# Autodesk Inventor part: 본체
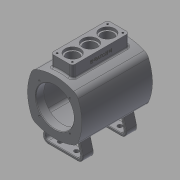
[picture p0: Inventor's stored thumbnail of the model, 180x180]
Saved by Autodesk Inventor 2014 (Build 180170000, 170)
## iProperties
Created: 2015-11
Part Number: 본체
Material: 일반
Document SubType Name: Modeling
Designer: mduedu
Density: 1 g/cm^3
Appearance: 기본값
Mass: 409.502 g
Surface Area: 1165.94 cm^2
Volume: 409.502 cm^3
Author: mduedu
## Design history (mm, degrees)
sketch "스케치2"
  geometry: L1 (0, 250)-(0, -250); L2 (250, 0)-(-250, 0); L3 (-50, 50)-(50, 50); L4 (50, 50)-(50, -50); L5 (50, -50)-(-50, -50); L6 (-50, -50)-(-50, 50); A1 r 90 centre (-40, 0) between (40.415, -40.415) and (40.415, 40.415); A2 r 90 centre (40, 0) between (-40.415, 40.415) and (-40.415, -40.415); A3 r 90 centre (0, -40) between (40.415, 40.415) and (-40.415, 40.415); A4 r 90 centre (0, 40) between (-40.415, -40.415) and (40.415, -40.415); 2 further points
  constraints: 12 end point, 8 point on circle, 4 centre point, 4 tangent, 3 perpendicular, 2 horizontal alignment, 2 midpoint, 2 parallel, 2 symmetric about line, 1 coincident, 1 equal radius, 1 horizontal, 1 vertical, 1 vertical alignment, 2 other
  dimensions: "d6" = 500 distance of L1.start L1.end; "d8" = 500 distance of L2.start L2.end; "d9" = 100 distance of L3.end L4.end; "d11" = 90 radius of A3
extrude "돌출1" new body sketch "스케치2" stored distance "d12" = 130; taper "d13" = 0 deg
fillet "모깎기6" dims "d30" = 15
feature "쉘1" dims "d31" = 15, "d32" = 6, "d33" = 15
sketch "스케치5"
  geometry: C1 r 35 at (0, 0); 1 further point
  constraints: 1 centre point, 1 coincident
  dimensions: "d34" = 70 diameter of C1
extrude "돌출3" cut sketch "스케치5" stored distance "d36" = 3; taper "d37" = 0 deg
fillet "모깎기14" dims "d78" = 3
sketch "스케치12"
  geometry: L1 (0, 0)-(28.284, 28.284); L2 (0, 0)-(40, 0); A1 r 40 centre (0, 0) between (28.284, 28.284) and (40, 0); 2 further points
  constraints: 4 end point, 2 coincident, 2 point on circle, 1 centre point, 1 horizontal
  dimensions: "d79" = 80 diameter of A1; "d80" = 45 deg angle of L2 L1
hole "구멍2" sketch "스케치12" at (28.284, 28.284) diameter "d82" = 3.242; stored, may be unused: countersink angle "d86" = 90 deg, drill point angle "d88" = 118 deg; dims "d83" = 9, "d84" = 10, "d85" = 2, "d87" = 11
node "작업 평면2"
sketch "스케치13"
  geometry: L1 (-52.5, -20)-(52.5, -20); L2 (52.5, -20)-(52.5, 20); L3 (52.5, 20)-(-52.5, 20); L4 (-52.5, 20)-(-52.5, -20); L5 (-52.5, -20)-(52.5, 20); L6 (52.5, -20)-(-52.5, 20); 1 further point
  constraints: 12 end point, 2 midpoint, 2 parallel, 1 horizontal, 1 perpendicular
  dimensions: "d93" = 105 distance of L2.end L3.end; "d95" = 40 distance of L1.end L2.end
extrude "돌출8" join sketch "스케치13" stored distance "d96" = 80; taper "d97" = 0 deg
fillet "모깎기15" dims "d98" = 5
fillet "모깎기16" dims "d99" = 3
sketch "스케치14"
  geometry: L1 (-52.5, 15)-(-52.5, -15) reference; L2 (52.5, -15)-(52.5, 15) reference; L3 (-52.5, 0)-(52.5, 0); 4 further points
  constraints: 2 end point, 2 midpoint, 2 point on line, 1 coincident
  dimensions: "d100" = 32 distance of point (-32, 0) point (0, 0); "d102" = 32 distance of point (32, 0) point (0, 0) (derived)
hole "구멍3" sketch "스케치14" at (-32, 0), (0, 0), (32, 0) diameter "d103" = 22; stored, may be unused: countersink angle "d107" = 90 deg, drill point angle "d109" = 118 deg; dims "d104" = 8, "d105" = 28, "d106" = 5, "d108" = 10
sketch "스케치15"
  geometry: L1 (46.5, -14)-(-46.5, -14); L2 (-46.5, -14)-(-46.5, 14); L3 (-46.5, 14)-(46.5, 14); L4 (46.5, 14)-(46.5, -14); L5 (46.5, -14)-(-46.5, 14); L6 (-46.5, -14)-(46.5, 14); L7 (47.5, 20)-(-47.5, 20) reference; L8 (-52.5, 15)-(-52.5, -15) reference; 5 further points
  constraints: 12 end point, 4 coincident, 2 midpoint, 2 parallel, 1 horizontal, 1 perpendicular
  dimensions: "d110" = 6 distance between parallel lines of L3 L7; "d111" = 6 distance between parallel lines of L2 L8
hole "구멍4" sketch "스케치15" at (-46.5, 14), (46.5, 14), (46.5, -14), (-46.5, -14) diameter "d112" = 3.242; stored, may be unused: countersink angle "d116" = 90 deg, drill point angle "d118" = 118 deg; dims "d113" = 10, "d114" = 28, "d115" = 5, "d117" = 13
sketch "스케치16"
  geometry: L1 (33.5, 0)-(61.5, 0) reference; 2 further points
  constraints: 1 vertical alignment, 1 other
  dimensions: "d128" = 11 distance from line of L1 point (47.5, -11)
feature "엠보싱2" sketch "스케치16" dims "d6" = 500, "d8" = 500, "d9" = 100, "d11" = 90, "d34" = 70, "d123" = 0.5, "d124" = 0
chamfer "모따기1" distance "d125" = 1; stored, may be unused: second distance "d126" = 2, angle "d127" = 45 deg
sketch "스케치18"
  geometry: L1 (0, 0)-(0, -80); L2 (40, -80)-(30.531, -44.663); L3 (-40, -80)-(-30.531, -44.663); L4 (-40, -80)-(40, -80); A1 r 90 centre (0, 40) between (-34.941, -42.941) and (34.941, -42.941) reference; A2 r 90 centre (0, 40) between (-30.531, -44.663) and (30.531, -44.663)
  constraints: 8 end point, 3 point on circle, 2 symmetric about line, 1 centre point, 1 coincident, 1 midpoint, 1 perpendicular, 1 vertical
  dimensions: "d132" = 80 distance of L3.start L2.start; "d134" = 75 deg angle of L4 L2; "d136" = 80 distance of L1.start L1.end
extrude "돌출9" new body sketch "스케치18" stored distance "d137" = 100; taper "d138" = 0 deg
fillet "모깎기17" dims "d139" = 10
sketch "스케치19"
  geometry: L1 (26.968, -80)-(-26.968, -80) reference; L2 (-36.627, -67.412)-(-30.531, -44.663) reference; L3 (30.531, -44.663)-(36.627, -67.412) reference; L4 (-25.775, -46.23)-(-31.797, -68.706); L5 (-26.968, -75)-(26.968, -75); L6 (31.797, -68.706)-(25.775, -46.23); L7 (0, 0)-(0, -80); A1 r 10 centre (26.968, -70) between (26.968, -80) and (36.627, -67.412) reference; A2 r 10 centre (-26.968, -70) between (-36.627, -67.412) and (-26.968, -80) reference; A3 r 90 centre (0, 40) between (-30.531, -44.663) and (30.531, -44.663) reference; A4 r 5 centre (-26.968, -70) between (-31.797, -68.706) and (-26.968, -75); A5 r 5 centre (26.968, -70) between (26.968, -75) and (31.797, -68.706); A6 r 90 centre (0, 40) between (-25.775, -46.23) and (25.775, -46.23)
  constraints: 8 end point, 7 point on circle, 3 centre point, 2 parallel, 1 coincident, 1 midpoint, 1 symmetric about line, 1 tangent, 2 other
  dimensions: "d140" = 5 distance between parallel lines of L1 L5
extrude "돌출10" cut sketch "스케치19" stored distance "d141" = 100; taper "d142" = 0 deg
sketch "스케치20"
  geometry: L1 (-30, 0)-(30, 0); L2 (30, 0)-(30, -90); L3 (30, -90)-(-30, -90); L4 (-30, -90)-(-30, 0); L5 (50, -80)-(-50, -80) reference; 2 further points
  constraints: 8 end point, 2 parallel, 1 coincident, 1 horizontal, 1 midpoint, 1 perpendicular
  dimensions: "d143" = 10 distance from line of L5 L2.end; "d144" = 60 distance of L2.end L3.end
extrude "돌출11" cut sketch "스케치20" stored distance "d145" = 100; taper "d146" = 0 deg
sketch "스케치21"
  geometry: L1 (0, 26.968)-(100, 26.968); L2 (100, 53.935)-(100, 0) reference; L3 (0, 0)-(0, 53.935) reference; L4 (0, 53.935)-(20, 53.935) reference; L5 (20, 0)-(0, 0) reference; L6 (115, 76.968)-(-15, 76.968) reference; L7 (115, -23.032)-(-15, -23.032) reference; L8 (10, 53.935)-(10, 0); L9 (50, 76.968)-(50, -23.032); C1 r 4 at (10, 41.968); C2 r 4 at (10, 11.968); C3 r 4 at (90, 41.968); C4 r 4 at (90, 11.968); 2 further points
  constraints: 6 end point, 6 midpoint, 4 centre point, 3 symmetric about line, 1 coincident, 1 horizontal, 1 point on line, 3 other
  dimensions: "d147" = 8 diameter of C1; "d148" = 15 distance from line of C1.centre L1
extrude "돌출12" cut sketch "스케치21" stored distance "d149" = 100; taper "d150" = 0 deg
feature "결합2"
  node "솔리드3"
fillet "모깎기18" dims "d151" = 1
fillet "모깎기19" dims "d152" = 2
node "솔리드1"
pattern_circular "원형 패턴1" dims angle "d90" = 360 deg
mirror "대칭3"
node "투영된 루프1"
